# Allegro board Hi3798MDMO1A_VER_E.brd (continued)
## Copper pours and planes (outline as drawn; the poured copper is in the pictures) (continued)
3V3_MOS on BOTTOM (solid shape): 22.19,60.75 22.19,56.94 22.06,56.82 19.9,56.82 19.77,56.94 19.77,57.15 21.81,57.15 21.81,57.53 21.43,57.53 21.43,57.15 19.77,57.15 19.77,58.67 20.54,58.67 20.54,59.05 20.16,59.05 20.16,58.67 19.77,58.67 19.77,59.31 20.54,59.31 20.54,59.69 20.16,59.69 20.16,59.31 19.77,59.31 19.77,60.75 19.9,60.88 22.06,60.88
3V3_MOS on BOTTOM (solid shape): 56.75,43.84 56.75,42.95 56.55,42.74 55.3,42.74 55.28,42.77 55.28,42.85 55.91,42.85 55.91,43.1 55.66,43.1 55.66,42.85 55.28,42.85 55.28,43.23 56.55,43.23 56.55,43.48 56.3,43.48 56.3,43.23 55.28,43.23 55.28,43.3 55.33,43.35 55.79,43.35 55.99,43.56 55.99,43.81 56.07,43.89 56.7,43.89
3V3_MOS on BOTTOM (solid shape): 57.69,45.21 57.69,44.98 57.92,44.75 58.46,44.75 58.52,44.69 58.52,44.25 58.72,44.05 58.8,44.05 58.96,43.89 58.96,43.1 58.84,42.97 57.97,42.97 57.82,43.12 57.82,43.18 58.39,43.18 58.39,43.43 58.01,43.43 58.01,43.18 57.82,43.18 57.82,43.89 57.64,44.07 58.39,44.07 58.39,44.32 58.01,44.32 58.01,44.07 57.64,44.07 57.01,44.7 57.01,45.21 57.06,45.26 57.64,45.26
3V3_MOS on BOTTOM (solid shape): 63.92,43.79 63.92,43.58 64.07,43.43 64.6,43.43 64.75,43.28 64.75,42.83 64.97,42.62 66.99,42.62 67.37,43 67.37,43.28 67.5,43.4 69.66,43.4 69.71,43.35 69.71,42.57 69.63,42.49 68.18,42.49 67.31,41.62 65.38,41.62 65.36,41.64 65.32,41.67 65.28,41.7 65.23,41.72 65.18,41.73 65.13,41.74 65.08,41.73 65.03,41.72 64.98,41.71 64.93,41.68 64.89,41.65 64.86,41.61 64.83,41.57 64.81,41.52 64.79,41.47 64.79,41.45 64.56,41.22 64.23,41.22 64.11,41.35 64.11,41.64 63.92,41.83 63.53,41.83 63.1,42.26 63.1,43.18 63.85,43.18 63.85,43.46 63.54,43.46 63.54,43.18 63.1,43.18 63.1,43.76 63.18,43.84 63.28,43.84 63.31,43.86 63.84,43.86
3V3_MOS on POWER03 (solid shape): outline of 8597 points within 16.8,9.7 77.96,72.44
3V3_MOS_FLASH on TOP (solid shape): 78.83,52.96 78.83,49.02 78.2,48.39 78.2,47.12 78.07,46.99 75.41,46.99 75.28,47.12 75.28,48.51 75.41,48.64 76.42,48.64 76.68,48.9 76.68,51.56 76.42,51.82 75.53,51.82 75.41,51.94 75.41,52.96 75.53,53.09 78.71,53.09
3V3_MOS_FLASH on BOTTOM (solid shape): outline of 367 points within 76.55,23.24 91.6,51.31
3V3_SD on TOP (solid shape): 13.7,56.21 13.7,55.19 13.55,55.04 11.34,55.04 11.26,55.11 11.26,55.8 11.34,55.88 12.76,55.88 12.89,56 12.89,56.21 13.04,56.36 13.55,56.36
3V3_SD on BOTTOM (solid shape): 17.74,55.93 17.75,55.93 17.81,55.86 20.35,55.86 20.41,55.8 20.41,52.88 20.28,52.75 18.88,52.75 18.76,52.88 18.76,54.15 18.63,54.28 16.47,54.28 15.71,55.04 13.04,55.04 12.92,55.16 12.92,56.31 13.04,56.43 17.23,56.43
3V3_WIFI on TOP (solid shape): 26.32,30.78 26.32,28.75 26.2,28.62 25.82,28.62 24.26,27.07 24.23,27.07 24.12,27.08 24.02,27.05 23.91,26.98 23.84,26.87 23.82,26.84 23.62,26.84 23.6,26.87 23.28,27.08 22.95,26.87 22.93,26.84 17.05,26.84 16.93,26.97 16.93,27.73 17.43,28.24 23.28,28.24 24.04,29 24.04,30.78 24.29,31.03 26.07,31.03
3V3_WIFI on BOTTOM (solid shape): 17.81,37 17.81,33.7 18.58,32.94 18.58,27.99 19.08,27.48 20.74,27.48 21.12,27.1 21.12,25.45 20.99,25.32 20.23,25.32 19.47,26.08 16.8,26.08 16.29,26.59 16.29,37 16.54,37.26 17.56,37.26
5V0 on TOP (solid shape): 85.44,80.64 85.44,77.09 84.55,76.2 81.37,76.2 80.68,75.51 80.68,56.39 80.45,56.16 72.72,56.16 72.36,56.52 75.79,56.52 75.79,56.9 75.41,56.9 75.41,56.52 75.15,56.52 75.15,56.9 74.77,56.9 74.77,56.52 70.07,56.52 70.02,56.56 70.02,57.28 70.15,57.4 72.99,57.4 73.5,57.91 77.44,57.91 77.69,58.17 77.69,64.07 76.62,65.15 76.62,65.71 77.38,65.71 77.38,66.09 77,66.09 77,65.71 76.62,65.71 76.62,66.34 77.38,66.34 77.38,66.72 77,66.72 77,66.34 76.62,66.34 76.62,74.85 80.55,78.79 80.55,79.49 82.31,81.25 84.83,81.25
5V0 on BOTTOM (solid shape): 85.63,80.5 85.63,77 85.38,76.74 81.41,76.74 79.92,75.25 79.92,69.03 79.69,68.8 77.63,68.8 77.38,69.06 77.38,75.91 81.25,79.78 81.25,80.47 82.33,81.55 84.59,81.55
5V0 on BOTTOM (solid shape): 74.21,16.67 74.21,16.67 74.28,16.6 74.78,16.6 75.02,16.36 75.02,16.33 75.15,16.21 75.15,16.1 75.18,16.08 75.76,16.08 75.84,16 75.84,14.51 75.73,14.4 75.73,14.24 75.5,14.02 74.99,14.02 74.91,13.94 74.91,13.15 74.76,13 73.69,13 73.57,13.13 73.57,16.68 73.69,16.81 74.06,16.81
5V0 on POWER03 (solid shape): outline of 898 points within 73.57,13.25 83.85,61.42
5V0_MOS on TOP (solid shape): 84.3,74.4 83.53,73.63 81.02,73.63 80.98,73.67 80.98,75.3 81.55,75.87 84.3,75.87
5V0_MOS on TOP (solid shape): 69.4,66.28 69.4,65.14 68.77,64.51 67.88,64.51 67.75,64.63 67.75,65.52 67.88,65.65 68.64,65.65 68.89,65.9 68.89,66.28 69.02,66.41 69.27,66.41
5V0_MOS on TOP (solid shape): 78.29,14.28 78.29,10.69 78.19,10.59 76.49,10.59 76.34,10.74 76.34,13.86 76.46,13.99 76.49,14 76.5,14 76.79,14.07 76.94,14.33 77.02,14.41 78.16,14.41
5V0_MOS on BOTTOM (solid shape): 79.79,17.83 79.79,12.75 79.41,12.37 77.63,12.37 77.43,12.57 77.43,13.97 77.78,14.33 78.2,14.33 78.48,14.61 78.48,16.87 78.28,17.07 75.9,17.07 75.89,17.06 74.58,17.06 74.33,17.32 74.33,19.1 74.58,19.35 78.27,19.35
5V0_MOS on POWER03 (solid shape): outline of 3205 points within 51.02,16.96 83.28,77.39
AVDD11_PLL012 on BOTTOM (solid shape): 62.26,37.46 62.26,36.9 62.39,36.77 63.1,36.77 63.13,36.75 63.13,35.96 63.23,35.86 63.48,35.86 63.51,35.83 63.51,35.15 63.48,35.12 62.67,35.12 62.56,35.24 62.56,36.07 62.96,36.07 62.96,36.32 62.71,36.32 62.71,36.07 62.56,36.07 62.56,36.25 62.44,36.37 61.78,36.37 61.71,36.44 61.71,36.75 62.14,36.75 62.14,37 61.88,37 61.88,36.75 61.71,36.75 61.71,37.46 61.73,37.49 62.24,37.49
AVDD11_USB3 on TOP (solid shape): 62.52,35.53 62.52,34.49 62.44,34.41 62.19,34.41 61.32,35.28 61.32,35.53 61.4,35.61 62.44,35.61
AVDD11_USB3 on BOTTOM (solid shape): 62.14,35.33 62.14,34.82 62.09,34.77 61.73,34.77 61.63,34.67 61.63,34.51 61.71,34.44 62.21,34.44 62.21,33.96 61.6,33.96 61.55,34.01 60.51,34.01 60.08,34.44 60.08,35.05 60.8,35.05 60.8,35.43 60.42,35.43 60.42,35.05 60.08,35.05 60.08,35.73 60.11,35.76 61.71,35.76
AVDD33_ADAC on BOTTOM (solid shape): 64.04,45.87 64.04,45.06 64.13,44.97 64.72,44.97 64.75,44.93 64.75,43.73 64.58,43.56 64.17,43.56 64.04,43.68 64.04,44.01 63.99,44.07 64.48,44.07 64.48,44.58 64.23,44.58 64.23,44.07 63.99,44.07 63.92,44.14 63.38,44.14 63.37,44.15 63.19,44.15 63.1,44.24 63.1,44.45 63.85,44.45 63.85,44.83 63.47,44.83 63.47,44.45 63.1,44.45 63.1,44.88 62.92,45.06 62.92,45.87 62.98,45.92 63.99,45.92
AVDD33_PLL01 on BOTTOM (solid shape): 68.11,37.38 68.11,35.94 67.9,35.73 67.9,35.45 67.42,34.97 65.74,34.97 65.49,35.23 65.95,35.23 65.95,35.43 67.53,35.43 67.53,35.81 67.15,35.81 67.15,35.43 65.95,35.43 65.95,35.48 65.69,35.48 65.69,35.23 65.49,35.23 65.26,35.45 64.12,35.45 64.04,35.53 64.04,35.89 64.19,36.04 64.8,36.04 64.82,36.03 65.5,36.03 65.92,35.61 66.73,35.61 67.12,35.99 67.12,37.54 67.19,37.61 67.88,37.61
AVDD33_USB2 on BOTTOM (solid shape): 67.42,41.02 67.42,40.25 67.34,40.18 65.62,40.18 65.01,39.57 64.22,39.57 64.09,39.7 64.09,39.9 64.25,40.05 64.63,40.05 64.96,40.38 64.96,40.64 65.3,40.98 66.39,40.98 66.48,41.07 67.37,41.07
GND on TOP (solid shape): 78.77,41.34 78.77,38.81 78.39,38.43 75.55,38.43 74.9,39.08 74.9,41.02 75.53,41.66 78.45,41.66
GND on TOP (solid shape): 72.87,52.1 72.87,49.75 72.75,49.63 72.42,49.63 72.37,49.68 72.37,50.52 72.32,50.57 70.7,50.57 70.68,50.59 70.68,51.15 70.7,51.18 72.29,51.18 72.34,51.23 72.34,52.09 72.49,52.24 72.72,52.24
GND on TOP (solid shape): 72.48,61.47 72.48,60.2 72.1,59.82 72.1,59.31 71.98,59.18 69.94,59.18 69.74,58.98 69.74,55.8 69.56,55.63 67.28,55.63 67.13,55.78 67.13,60.2 67.63,60.71 71.09,60.71 71.09,61.21 70.58,61.21 70.58,60.71 67.63,60.71 68.52,61.59 72.36,61.59
GND on TOP (solid shape): 68.69,68.29 68.69,66.08 68.51,65.9 67.62,65.9 67.5,66.03 67.5,67.05 67.36,67.18 67.91,67.18 67.91,67.56 67.53,67.56 67.53,67.18 67.36,67.18 67.24,67.3 67.24,68.14 67.29,68.19 67.8,68.19 68.08,68.47 68.51,68.47
GND on TOP (solid shape): 55.99,68.09 55.99,67.48 56.52,66.95 56.52,66.08 56.78,65.83 57.39,65.83 57.57,65.65 57.57,61.33 58,60.9 58.5,60.9 58.53,60.89 58.55,60.88 58.56,60.85 58.56,60.09 58.02,59.56 58.02,58.34 57.87,58.18 57.69,58.18 54.57,61.31 54.57,66.21 56.17,66.21 56.17,66.59 55.79,66.59 55.79,66.21 54.57,66.21 54.57,67.96 54.72,68.12 55.96,68.12
GND on TOP (solid shape): 19.66,46.56 19.66,44.62 19.53,44.49 18.51,44.49 18,43.98 18,42 18.13,41.87 22.13,41.87 22.36,42.1 23.28,42.1 23.44,41.94 23.44,38.95 23.3,38.81 20.67,38.81 20.59,38.88 20.59,39.42 21.37,39.42 21.37,39.8 20.99,39.8 20.99,39.42 20.59,39.42 20.59,40.36 19.86,41.09 18.19,41.09 18.05,40.95 18.05,40.03 17.95,39.93 17.55,39.93 17.43,40.05 17.43,40.95 17.3,41.08 15.95,41.08 15.87,41.16 15.87,41.73 15.94,41.8 17.18,41.8 17.46,42.08 17.46,44.1 17.96,44.59 17.96,46.59 18.11,46.74 19.48,46.74
GND on TOP (solid shape): 63.21,31.66 63.22,31.65 63.29,31.55 63.4,31.48 63.41,31.48 63.47,31.42 63.47,31.23 63.3,31.07 63.3,30.14 63.27,30.1 63.24,30.09 63.22,30.09 63.03,30.09 62.88,29.99 62.87,29.98 62.84,29.97 62.3,29.97 62.07,30.2 62.07,30.31 61.84,30.55 61.83,30.57 61.83,30.59 61.74,30.81 61.51,30.9 61.47,30.92 61.46,30.96 61.46,31.01 61.54,31.09 61.56,31.09 61.68,31.14 61.79,31.24 61.81,31.24 62.03,31.24 62.05,31.24 62.07,31.22 62.34,31.09 62.59,31.25 62.59,31.25 62.81,31.47 62.82,31.48 62.94,31.54 63.02,31.65 63.04,31.67 63.07,31.67 63.19,31.67
GND on TOP (solid shape): 86.32,18.08 86.41,18.05 87.58,16.88 87.58,11.3 88.99,9.89 88.99,8.32 85.78,8.49 87.82,6.01 87.25,5.44 84.56,5.44 84.29,5.72 84.29,7.97 85.1,8.78 85.55,8.78 85.57,8.78 86.94,10.15 86.94,14.49 86.65,14.79 86.65,16.18 85.89,16.94 85.89,17.01 85.91,17.03 85.98,17.09 86.04,17.15 86.25,17.56 86.24,18.01
GND on TOP (solid shape): outline of 110 points within 30.83,30.23 44.67,38.3
GND on TOP (solid shape): outline of 85 points within 84.87,35.18 87.77,38.09
GND on TOP (solid shape): outline of 383 points within 63.66,37.51 68.55,46.78
GND on TOP (solid shape): outline of 2782 points within 48.84,26.97 77.05,47.34
GND on TOP (solid shape): outline of 4330 points within 10.64,0.51 96.12,87.84
GND on BOTTOM (solid shape): 17.27,58.39 17.27,56.98 17.23,56.94 13.04,56.94 12.92,57.07 12.92,57.65 13.09,57.83 14.67,57.83 15.39,58.56 17.11,58.56
GND on BOTTOM (solid shape): 67.76,17.92 68.36,17.92 68.45,17.83 68.45,16.18 70.92,13.71 70.92,12.92 70.33,12.32 68.97,12.32 67.84,13.45 67.84,15.19 66.67,16.36 66.67,17.4 67.4,17.4 67.4,17.78 67.02,17.78 67.02,17.4 66.67,17.4 66.67,18.15 67.52,18.15
GND on BOTTOM (solid shape): 42.35,46.37 42.35,45.91 42.34,45.89 42.32,45.88 42.28,45.84 42.25,45.81 42.22,45.76 42.2,45.72 42.19,45.67 42.18,45.62 42.18,45.57 42.19,45.52 42.2,45.47 42.23,45.43 42.26,45.39 42.27,45.37 42.28,45.35 42.28,45.04 42.18,44.94 41.59,44.94 41.51,44.86 41.51,44.53 41.39,44.41 41.26,44.41 41.11,44.56 41.11,45.4 41.9,45.4 41.9,45.66 41.51,45.66 41.51,45.4 41.11,45.4 41.11,45.75 41.14,45.78 42.02,45.78 42.02,46.04 41.64,46.04 41.64,45.78 41.14,45.78 41.8,46.44 42.28,46.44
GND on BOTTOM (solid shape): outline of 144 points within 38.31,28.83 46.24,43.43
GND on BOTTOM (solid shape): outline of 7927 points within 10.64,0.51 96.12,87.84
GND on GND02 (solid shape): outline of 24161 points within 10.64,0.51 96.12,87.84
GND on POWER03 (solid shape): 62.45,25.15 62.45,21.46 64.86,19.05 69.44,19.05 69.69,18.8 69.69,14.03 69.32,13.65 69.32,12.84 69.17,12.7 66.01,12.7 60.55,7.24 33.5,7.24 23.97,16.76 23.97,24.77 24.1,24.89 26.89,24.89 27.02,24.77 27.02,18.8 35.02,10.79 47.59,10.79 62.07,25.27 62.32,25.27
GND on POWER03 (solid shape): outline of 1558 points within 38.45,23.75 54.58,47.24
GND on POWER03 (solid shape): outline of 4401 points within 10.64,0.51 96.12,87.84
VDD_AUDIO on TOP (solid shape): 66.98,68.04 66.98,67.17 67.23,66.92 67.23,64.63 67.1,64.51 65.96,64.51 65.83,64.63 65.83,67.18 66.64,67.18 66.64,67.56 66.26,67.56 66.26,67.18 65.83,67.18 65.83,68.02 65.95,68.14 66.87,68.14
FE_3V3 on BOTTOM (solid shape): 51.6,45.36 52.08,45.36 52.37,45.07 52.37,44.23 52.59,44.01 52.59,43.63 52.51,43.56 52.05,43.56 51.95,43.66 51.95,44.57 51.82,44.7 51.19,44.7 50.96,44.47 50.96,43.89 50.94,43.86 50.4,43.86 50.33,43.94 50.33,45.54 50.48,45.69 51.27,45.69
HDMI_TX_1V1 on BOTTOM (solid shape): 61.58,43.63 61.58,43.1 61.53,43.05 61.38,43.05 61.02,42.69 61.02,41.98 61.12,41.88 61.45,41.88 61.53,41.8 61.53,41.12 61.4,40.99 60.82,40.99 60.61,40.79 60.61,40.23 60.56,40.18 59.85,40.18 59.85,40.51 60.42,40.51 60.42,40.89 60.04,40.89 60.04,40.51 59.85,40.51 59.85,40.69 59.88,40.71 59.88,41.32 59.88,41.37 59.88,41.42 59.88,41.45 59.88,41.63 59.77,41.73 59.59,41.73 59.57,41.73 59.52,41.74 59.48,41.73 59.45,41.73 59.22,41.73 59.19,41.75 59.19,42.04 60.67,42.04 60.67,42.42 60.29,42.42 60.29,42.04 59.19,42.04 59.19,42.57 59.22,42.59 60.28,42.59 61.04,43.35 61.04,43.63 61.07,43.66 61.55,43.66
HDMI_TX_3V3 on BOTTOM (solid shape): 59.01,45.36 59.01,44.88 59.17,44.72 60.54,44.72 60.56,44.7 60.56,43.74 60.53,43.72 60.51,43.67 60.48,43.64 60.39,43.58 60.32,43.57 60.26,43.58 60.2,43.6 60.15,43.64 60.11,43.68 60.08,43.72 60.08,44.14 60.03,44.19 58.91,44.19 58.71,44.39 58.71,44.77 58.48,45 57.87,45 57.84,45.03 57.84,45.51 57.87,45.54 58.84,45.54
Net_61 on BOTTOM (solid shape): outline of 318 points within 0.51,0.51 7.62,87.84
Net_62 on BOTTOM (solid shape): outline of 208 points within 99.14,0.51 106.25,87.84
Net_63 on POWER03 (solid shape): outline of 264 points within 0.51,0.51 7.62,87.84
Net_64 on POWER03 (solid shape): outline of 178 points within 99.14,0.51 106.25,87.84
Net_65 on GND02 (solid shape): outline of 264 points within 0.51,0.51 7.62,87.84
Net_66 on GND02 (solid shape): outline of 178 points within 99.14,0.51 106.25,87.84
Net_67 on TOP (solid shape): outline of 322 points within 0.51,0.51 7.62,87.84
Net_68 on TOP (solid shape): outline of 208 points within 99.14,0.51 106.25,87.84
Net_141 on BOTTOM (solid shape): 35.47,81 32.8,81 32.8,82.27 35.47,82.27
Net_142 on BOTTOM (solid shape): 23.91,81 21.24,81 21.24,82.27 23.91,82.27
Net_143 on BOTTOM (solid shape): 34.45,82.77 31.78,82.77 31.78,84.04 34.45,84.04
Net_144 on BOTTOM (solid shape): 22.89,82.77 20.23,82.77 20.23,84.04 22.89,84.04
USB01_1V1 on BOTTOM (solid shape): 57.54,41.63 57.68,41.63 57.68,41.62 58.08,41.62 58.15,41.55 58.15,41.25 58.07,41.17 57.51,41.17 57.41,41.07 57.41,39.34 57.39,39.31 56.85,39.31 56.83,39.34 56.83,39.8 57.31,39.8 57.31,40.43 57.06,40.43 57.06,39.8 56.83,39.8 56.83,41.07 57.31,41.07 57.31,41.32 57.06,41.32 57.06,41.07 56.83,41.07 56.83,41.78 56.85,41.8 57.36,41.8
USB01_3V3 on BOTTOM (solid shape): 55.14,45.73 55.14,44.97 55,44.83 55,42.77 54.97,42.74 54.44,42.74 54.36,42.82 54.36,43.23 54.9,43.23 54.9,43.48 54.64,43.48 54.64,43.23 54.36,43.23 54.36,44.12 54.9,44.12 54.9,44.37 54.64,44.37 54.64,44.12 54.36,44.12 54.36,44.7 54.21,44.85 54.21,45.64 54.34,45.77 55.1,45.77
VDAC_3V3 on BOTTOM (solid shape): 68.41,44.85 68.41,44.17 68.36,44.12 66.88,44.12 66.85,44.13 66.8,44.15 66.75,44.15 66.69,44.15 66.64,44.15 66.59,44.13 66.53,44.1 66.49,44.07 66.45,44.03 66.42,43.99 66.41,43.96 66.09,43.65 65.32,43.65 65.21,43.53 65.01,43.53 64.88,43.66 64.88,43.86 65.57,43.86 65.57,44.12 65.31,44.12 65.31,43.86 64.88,43.86 64.88,44.12 65.03,44.27 65.05,44.27 65.07,44.26 65.12,44.26 65.17,44.26 65.19,44.27 65.95,44.27 66.25,44.57 66.25,45.03 66.28,45.06 68.21,45.06
$4N777 on TOP (solid shape): 72.08,50.23 72.08,49.6 72.66,49.02 74.64,49.02 74.85,48.81 74.85,47.08 74.77,46.99 71.11,46.99 71.01,47.09 71.01,49.27 70.66,49.62 70.66,50.24 70.68,50.26 72.04,50.26
$4N814 on TOP (solid shape): 72.93,18.14 72.93,16.39 72.85,16.3 70.25,16.3 69.26,15.31 69.26,13.96 69.25,13.96 68.61,13.96 68.6,13.97 68.6,16.81 68.81,17.02 68.81,18.16 68.92,18.28 72.8,18.28
$4N882 on TOP (solid shape): 21.93,46.35 21.93,42.24 21.75,42.06 18.35,42.06 18.2,42.21 18.2,43.91 18.47,44.19 19.67,44.19 19.86,44.38 19.86,46.36 20.05,46.55 21.73,46.55
$4N983 on TOP (solid shape): 77.31,59.82 77.31,59.72 77.3,59.71 77.3,58.42 77.17,58.29 73.12,58.29 72.74,57.91 70.07,57.91 70.01,57.97 70.01,58.67 70.11,58.77 72.09,58.77 72.47,59.15 72.48,59.15 72.48,59.56 72.87,59.94 77.18,59.94
$14N488 on TOP (solid shape): 91.15,74.55 91.15,73.41 90.9,73.15 86.96,73.15 86.45,73.66 85.06,73.66 85.06,75.95 85.18,76.07 89.63,76.07
$14N488 on BOTTOM (solid shape): 93.77,72.57 93.77,62.84 88.56,57.63 85.13,57.63 84.7,58.06 84.7,59.36 85.03,59.69 87.06,59.69 91.38,64.01 91.38,71.37 89.38,73.38 89.38,74.68 89.63,74.93 91.41,74.93
$14N524 on TOP (solid shape): 79.92,8.56 81.44,8.56 81.7,8.3 81.7,6.78 81.44,6.52 79.54,6.52 78.39,5.38 76.49,5.38 76.36,5.51 76.36,9.95 76.49,10.08 78.39,10.08
$14N524 on BOTTOM (solid shape): 86.1,11.07 86.1,9.06 83.56,6.52 79.66,6.52 79.54,6.65 79.54,8.43 79.79,8.68 83.43,8.68 84.7,9.95 84.7,11.07 85.07,11.44 85.73,11.44
$15N771 on TOP (solid shape): 73.44,6.27 74.33,6.27 74.46,6.14 74.46,4.75 74.84,4.36 75.98,4.36 76.11,4.24 76.11,1.44 75.98,1.32 74.08,1.32 73.95,1.44 73.95,2.97 72.93,3.98 70.77,3.98 70.65,4.11 70.65,5.51 73.95,5.51 73.95,5.89 73.69,5.89 73.69,5.51 70.65,5.51 70.65,6.14 70.77,6.27 71.54,6.27 71.61,6.35 71.79,6.52 73.19,6.52
$15N777 on BOTTOM (solid shape): 19.27,62.2 19.27,56.82 19.14,56.69 18.12,56.69 17.93,56.88 17.93,58.67 19.02,58.67 19.02,59.05 18.64,59.05 18.64,58.67 17.93,58.67 17.93,59.31 19.02,59.31 19.02,59.69 18.64,59.69 18.64,59.31 17.93,59.31 17.93,59.94 17.93,59.95 17.74,60.14 17.74,62.15 17.94,62.35 19.11,62.35
$15N783 on BOTTOM (solid shape): 19.36,63.74 19.36,62.82 19.19,62.66 16.22,62.66 16.09,62.78 16.09,63.8 16.22,63.93 19.17,63.93
$17N177 on BOTTOM (solid shape): 33.79,72 33.79,70.42 33.66,70.29 24.72,70.29 24.62,70.39 24.62,71.06 24.72,71.16 31.83,71.16 31.99,71.31 31.99,72 32.17,72.17 33.61,72.17

Small or netless copper shapes (teardrops, artwork), in the pictures only: 3 on TOP

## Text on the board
Ref Des/Silkscreen Bottom: 0400 | 0350 | 1014 | 0375 | 0464 | 2013-05-29 | 2013-08-08 | 2013-09-26 | 2014-06-17 | 2014-06-20 | 2014-07-01 | 2014-07-14 | 2014-07-18 | 2014-08-12 | 2014-10-31 | 0113 | 0522 | 0483 | 0592 | UPDATE | VER.B | VER.C | VER.D | VER.A | VER.E | 01 | 113536 | 114626 | 115584 | 116241 | 120241 | 120317 | 120525 | 120803 | 120894 | 121248 | 122391 | A
Ref Des/Silkscreen Top: 113536 | 114626 | 115584 | 116241 | 120241 | 120317 | 120525 | 120803 | 120894 | 121248 | 122391 | 01 | VER.B | VER.C | VER.D | VER.A | VER.E | UPDATE | 0113 | 0522 | 0483 | 0592 | 2013-05-29 | 2013-08-08 | 2013-09-26 | 2014-06-17 | 2014-06-20 | 2014-07-01 | 2014-07-14 | 2014-07-18 | 2014-08-12 | 2014-10-31 | 0400 | 0350 | 1014 | 0375 | 0464 | HI3798MDMO1A VER.E
DIMENSION: 120525 | 120803 | 120894 | 121248 | 122391 | 120317 | 113536 | 114626 | 115584 | 116241 | REV | 01 | VER.A | VER.B | VER.C | VER.D | VER.E | UPDATE | 0592 | 0483 | 0113 | 0522 | 2014-07-01 | 2014-07-14 | 2014-07-18 | 2014-08-12 | 2014-10-31 | 2014-06-20 | 2013-05-29 | 2013-08-08 | 2013-09-26 | 1014 | 0464 | 0358 | 0400 | 0350 | HI3798MDMO1A VER.E | Hi-Tg | 150 | C | Single Impedance | Diff Impedance | 100 ohm | 90 ohm | 50 ohm | PREPREG | GND02 | ART01 | ART04 | POWWE03 | CORE | Layer | 1,4 | Trace Width(mil) | Trace W/S(mil) | 4.5/6.0 | 6.0/7.0 | Layer Stack up | Solder Bot | Silk Bot | 5 | Solder Top | Silk Top | Tolerance | + | - | 10% | Frequency(MHZ) | Default | Thickness (mil) | 1.8(0.5oz+plating) | 4.0 | 1.2(1.0oz) | XXX | Remark | Notes3: | For this PN,Soldermask should be covered at all required location and | no red solder(copper color) is allowed at BGA area | 15 | 8XR2[78]
User.10: FIGURE | SIZE | 8.0 | 10.0 | 20.0 | 30.0 | 32.0 | 36.0 | 38.0 | 40.0 | 52.0 | 90.0 | 95.0 | 142.0 | 43.0 | 80.0 | 135.0 | 52.0x24.0 | 60.0x32.0 | 82.0x36.0 | 96.0x26.0 | 96.0x30.0 | 105.0x36.0 | 116.0x30.0 | DRILL CHART: TOP to BOTTOM | ALL UNITS ARE IN MILS | PLATED | NON-PLATED | QTY | 450 | 880 | 4 | 9 | 3 | 13 | 18 | 2 | 32 | 5 | 1
